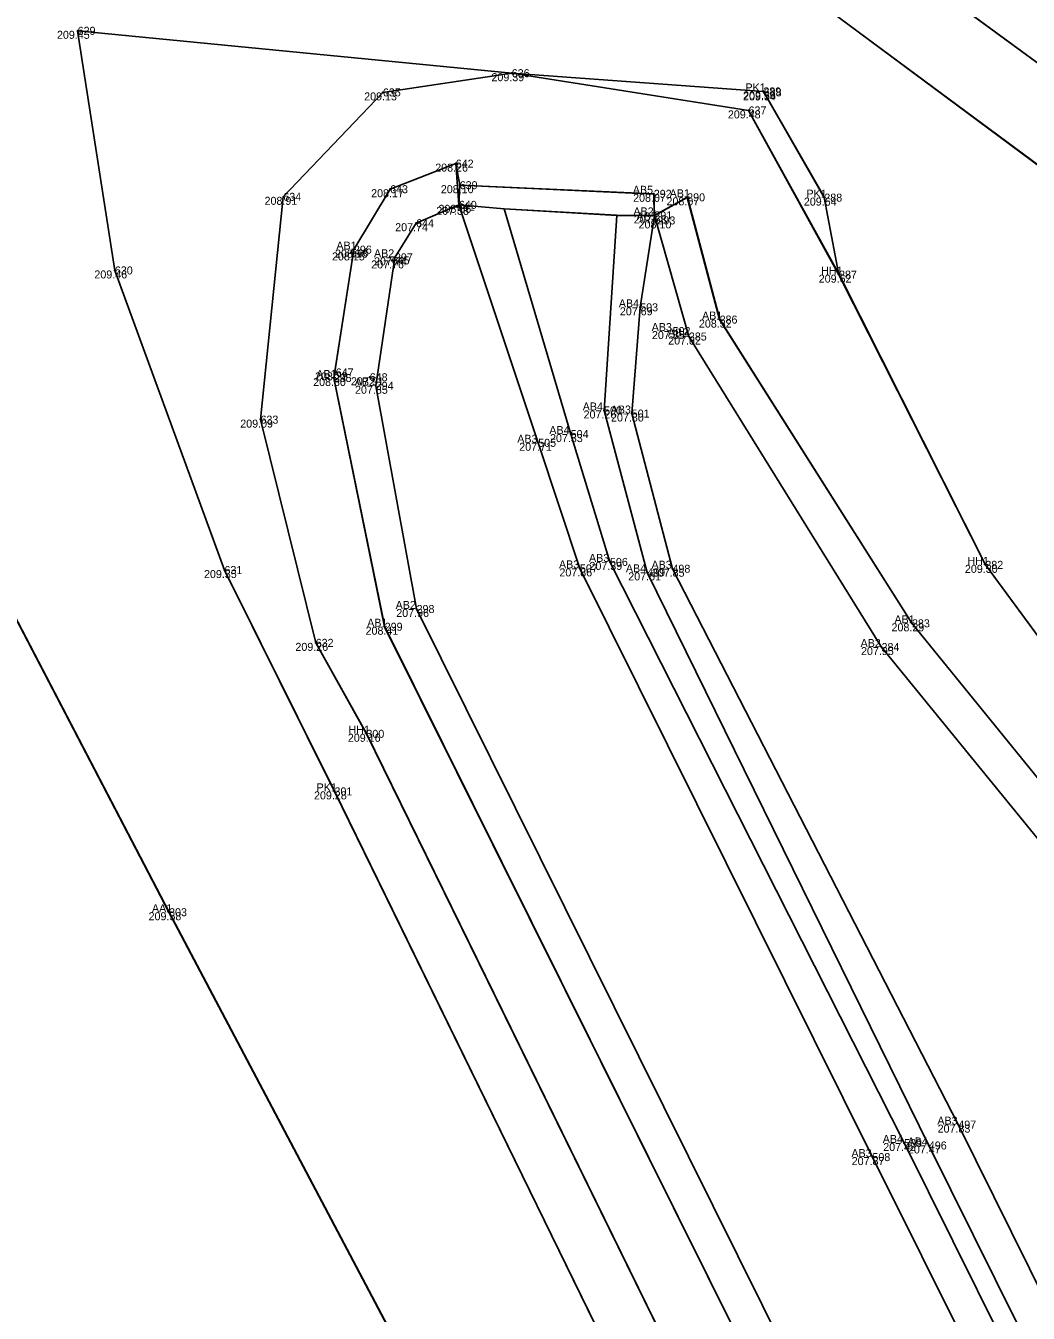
# Model space of a CAD drawing. Extents: x -263091 to -262565, y -1238731 to -1237092.
# Drawn here: x -262955.92 to -262930.86, y -1238442.76 to -1238410.57 of the extents above; entities that cross this region are included whole.
import ezdxf

# ---------------------------------------------------------------- set-up
doc = ezdxf.new("R2010")
doc.units = 0
for name, color, linetype in [('01_Hrana_betónu', 7, 'Continuous'), ('02_Oplotenie', 7, 'Continuous'), ('03_Asfalt', 7, 'Continuous'), ('05_Hrana_terénu', 7, 'Continuous'), ('07_Iné', 7, 'Continuous'), ('10', 7, 'Continuous'), ('Groma (21)', 7, 'Continuous'), ('Groma (22)', 7, 'Continuous'), ('Groma (23)', 7, 'Continuous'), ('Groma (24)', 7, 'Continuous'), ('U001_Betónové_panely_oblast', 7, 'Continuous'), ('U001_Betóny_prídavné', 7, 'Continuous'), ('U001_Zeleň_mimo', 7, 'Continuous'), ('U001_Zeleň_vnútro', 7, 'Continuous'), ('U001_Zeleň_zatrávňovač', 7, 'Continuous'), ('U002_Asfalt', 7, 'Continuous'), ('U002_Zeleň_mimo', 7, 'Continuous')]:
    doc.layers.add(name, color=color, linetype=linetype)

msp = doc.modelspace()

# ---------------------------------------------------------------- linework, layer by layer
at = {"layer": '01_Hrana_betónu'}
for points in [[(-262945.17, -1238414.02), (-262946.81, -1238414.66), (-262947.715, -1238416.17), (-262948.218, -1238419.379), (-262946.945, -1238425.597), (-262935.208, -1238449.194), (-262927.854, -1238464.094), (-262916.808, -1238486.576), (-262907.486, -1238505.358), (-262899.299, -1238522.3), (-262896.198, -1238529.903), (-262891.697, -1238541.993), (-262882.447, -1238561.681), (-262873.377, -1238580.679), (-262868.934, -1238589.993), (-262864.101, -1238600.869)], [(-262863.262, -1238600.529), (-262868.088, -1238589.608), (-262872.609, -1238580.269), (-262881.626, -1238561.239), (-262890.834, -1238541.618), (-262895.354, -1238529.529), (-262898.372, -1238521.954), (-262906.659, -1238504.862), (-262915.915, -1238486.239), (-262927.038, -1238463.656), (-262934.41, -1238448.791), (-262946.148, -1238425.153), (-262947.17, -1238419.573), (-262946.689, -1238416.363), (-262946.16, -1238415.51), (-262945.09, -1238415.05), (-262945.17, -1238414.02)], [(-262945.09, -1238415.05), (-262943.108, -1238420.999), (-262942.065, -1238424.139), (-262934.754, -1238438.855), (-262923.683, -1238461.06), (-262913.753, -1238481.232), (-262903.896, -1238501.06), (-262894.759, -1238519.856), (-262890.317, -1238530.551), (-262883.158, -1238545.169), (-262873.572, -1238564.111), (-262869.728, -1238571.951), (-262860.562, -1238590.864), (-262854.835, -1238604.812), (-262840.38, -1238642.586), (-262833.174, -1238661.935), (-262826.575, -1238681.018), (-262825.738, -1238690.053), (-262824.527, -1238692.082)], [(-262919.416, -1238445.121), (-262926.823, -1238435.554), (-262934.526, -1238426.105), (-262939.342, -1238418.342), (-262940.205, -1238415.315), (-262939.384, -1238414.863)], [(-262939.384, -1238414.863), (-262938.574, -1238417.919), (-262933.765, -1238425.512), (-262926.119, -1238434.921), (-262918.733, -1238444.559)], [(-262821.464, -1238691.979), (-262823.978, -1238691.385), (-262824.893, -1238689.953), (-262825.729, -1238680.825), (-262832.468, -1238661.625), (-262839.672, -1238642.452), (-262854.271, -1238604.655), (-262859.863, -1238590.55), (-262868.949, -1238571.69), (-262872.864, -1238563.867), (-262882.403, -1238544.934), (-262889.591, -1238530.296), (-262894.035, -1238519.557), (-262903.102, -1238500.748), (-262912.912, -1238480.97), (-262922.987, -1238460.594), (-262933.962, -1238438.502), (-262941.314, -1238423.977), (-262942.296, -1238420.781), (-262943.962, -1238415.15)], [(-262941.142, -1238415.313), (-262941.461, -1238420.191), (-262940.383, -1238424.238), (-262933.343, -1238438.564), (-262922.27, -1238460.876), (-262912.449, -1238480.877), (-262902.557, -1238500.683), (-262893.416, -1238519.552), (-262889.058, -1238529.686), (-262881.962, -1238544.577), (-262872.106, -1238564.019), (-262868.478, -1238571.232), (-262859.211, -1238590.61), (-262852.998, -1238605.343), (-262846.933, -1238621.173), (-262838.559, -1238643.348), (-262831.894, -1238661.158), (-262825.164, -1238680.62), (-262824.312, -1238689.696), (-262823.847, -1238690.483), (-262822.763, -1238690.91), (-262821.486, -1238690.803)], [(-262821.555, -1238690.42), (-262822.731, -1238690.203), (-262823.426, -1238689.509), (-262824.318, -1238680.43), (-262831.163, -1238660.976), (-262837.946, -1238643.111), (-262846.365, -1238620.94), (-262852.333, -1238605.156), (-262858.618, -1238590.245), (-262867.784, -1238570.905), (-262871.416, -1238563.68), (-262881.223, -1238544.283), (-262888.392, -1238529.442), (-262892.626, -1238519.239), (-262901.725, -1238500.385), (-262911.6, -1238480.51), (-262921.479, -1238460.51), (-262932.607, -1238438.043), (-262939.752, -1238424.147), (-262940.771, -1238420.267), (-262940.559, -1238417.612), (-262940.205, -1238415.315)]]:
    msp.add_lwpolyline(points, dxfattribs=at)
at = {"layer": '02_Oplotenie'}
msp.add_lwpolyline([(-262935.956, -1238414.87), (-262937.48, -1238412.215), (-262943.77, -1238411.76), (-262954.62, -1238410.7), (-262953.69, -1238416.69), (-262950.95, -1238424.18), (-262948.2, -1238429.713), (-262938.076, -1238450.416), (-262931.824, -1238462.793)], dxfattribs=at)
at = {"layer": '03_Asfalt'}
for points in [[(-262913.444, -1238391.676), (-262911.985, -1238397.337), (-262910.006, -1238403.107), (-262907.769, -1238409.039), (-262901.709, -1238424.56), (-262896.942, -1238436.871), (-262897.547, -1238437.016), (-262898.706, -1238436.381), (-262904.848, -1238431.522), (-262916.36, -1238422.355), (-262927.608, -1238413.712), (-262940.472, -1238404.296), (-262944.235, -1238401.54), (-262944.94, -1238400.579), (-262945.063, -1238399.495), (-262942.635, -1238399.58), (-262939.962, -1238399.183), (-262936.84, -1238398.276), (-262934.121, -1238396.673), (-262931.78, -1238394.73), (-262927.567, -1238384.599)], [(-262974.83, -1238389.493), (-262966.434, -1238405.689), (-262952.335, -1238432.734), (-262942.188, -1238451.946), (-262934.983, -1238466.187), (-262921.957, -1238491.107), (-262911.861, -1238511.116), (-262905.822, -1238523.977), (-262900.647, -1238535.669), (-262888.764, -1238565.07), (-262881.2, -1238585.494), (-262874.644, -1238603.324)], [(-262804.465, -1238690.033), (-262818.631, -1238655.736), (-262826.695, -1238636.389), (-262836.855, -1238611.872), (-262842.406, -1238598.306), (-262850.452, -1238578.707), (-262858.82, -1238561.234), (-262870.509, -1238539), (-262873.344, -1238533.53), (-262876.375, -1238529.239), (-262880.031, -1238521.826), (-262869.115, -1238517.45), (-262870.175, -1238508.052), (-262871.319, -1238501.744), (-262886.895, -1238462.375), (-262895.067, -1238441.663), (-262905.824, -1238433.621), (-262917.716, -1238423.993), (-262928.896, -1238415.327), (-262941.774, -1238405.784), (-262954.673, -1238396.412), (-262962.054, -1238391.026)]]:
    msp.add_lwpolyline(points, dxfattribs=at)
at = {"layer": '05_Hrana_terénu'}
msp.add_lwpolyline([(-262927.783, -1238467.254), (-262930.465, -1238462.525), (-262936.779, -1238449.928), (-262947.402, -1238428.273), (-262948.67, -1238426), (-262950.05, -1238420.42), (-262949.48, -1238414.85), (-262946.99, -1238412.24), (-262943.77, -1238411.76), (-262937.85, -1238412.69), (-262935.589, -1238416.796), (-262931.931, -1238424.05), (-262925.295, -1238433.06), (-262918.113, -1238442.283), (-262917.125, -1238443.234)], dxfattribs=at)
at = {"layer": '07_Iné'}
msp.add_lwpolyline([(-262945.07, -1238414.56), (-262945.09, -1238415.05), (-262945.09, -1238415.05), (-262943.962, -1238415.15), (-262941.142, -1238415.313), (-262940.205, -1238415.315), (-262940.205, -1238415.315), (-262940.219, -1238414.775)], close=True, dxfattribs=at)
at = {"layer": '10'}
msp.add_lwpolyline([(-262982.434, -1238375.977), (-262968.907, -1238386.238), (-262962.054, -1238391.026), (-262954.673, -1238396.412), (-262941.774, -1238405.784), (-262928.896, -1238415.327), (-262917.716, -1238423.993), (-262905.824, -1238433.621), (-262895.067, -1238441.663), (-262870.407, -1238460.6)], dxfattribs=at)
at = {"layer": 'Groma (21)'}
for centre in [(-262954.62, -1238410.7), (-262943.77, -1238411.76), (-262937.48, -1238412.215), (-262946.99, -1238412.24), (-262937.47, -1238412.24), (-262937.85, -1238412.69), (-262945.17, -1238414.02), (-262946.81, -1238414.66), (-262945.07, -1238414.56), (-262940.219, -1238414.775), (-262949.48, -1238414.85), (-262945.14, -1238415.1), (-262945.09, -1238415.05), (-262939.384, -1238414.863), (-262935.956, -1238414.87), (-262940.205, -1238415.315), (-262946.16, -1238415.51), (-262940.127, -1238415.44), (-262947.79, -1238416.24), (-262947.715, -1238416.17), (-262946.689, -1238416.363), (-262953.69, -1238416.69), (-262946.77, -1238416.44), (-262935.589, -1238416.796), (-262940.559, -1238417.612), (-262938.574, -1238417.919), (-262939.748, -1238418.206), (-262939.342, -1238418.342), (-262948.17, -1238419.24), (-262948.218, -1238419.379), (-262947.32, -1238419.36), (-262947.17, -1238419.573), (-262941.461, -1238420.191), (-262940.771, -1238420.267), (-262950.05, -1238420.42), (-262942.296, -1238420.781), (-262943.108, -1238420.999), (-262941.314, -1238423.977), (-262931.931, -1238424.05), (-262950.95, -1238424.18), (-262942.065, -1238424.139), (-262940.383, -1238424.238), (-262939.752, -1238424.147), (-262946.148, -1238425.153), (-262946.945, -1238425.597), (-262933.765, -1238425.512), (-262948.67, -1238426), (-262934.526, -1238426.105), (-262947.402, -1238428.273), (-262948.2, -1238429.713), (-262952.335, -1238432.734), (-262932.607, -1238438.043), (-262933.962, -1238438.502), (-262933.343, -1238438.564), (-262934.754, -1238438.855)]:
    msp.add_circle(centre, 0.01, dxfattribs=at)
at = {"layer": 'U001_Betónové_panely_oblast'}
msp.add_lwpolyline([(-262907.49, -1238505.36), (-262916.81, -1238486.58), (-262927.85, -1238464.09), (-262935.21, -1238449.19), (-262946.95, -1238425.6), (-262948.22, -1238419.38), (-262947.72, -1238416.17), (-262946.81, -1238414.66), (-262945.17, -1238414.02), (-262945.09, -1238415.05), (-262943.96, -1238415.15), (-262941.14, -1238415.31), (-262940.21, -1238415.32), (-262939.38, -1238414.86), (-262938.57, -1238417.92), (-262933.77, -1238425.51), (-262926.12, -1238434.92), (-262918.73, -1238444.56), (-262919.42, -1238445.12), (-262914.36, -1238451.38), (-262913.6, -1238450.89), (-262908.88, -1238459.13), (-262904.31, -1238470.05)], dxfattribs=at)
msp.add_lwpolyline([(-262907.49, -1238505.36), (-262916.81, -1238486.58), (-262927.85, -1238464.09), (-262935.21, -1238449.19), (-262946.95, -1238425.6), (-262948.22, -1238419.38), (-262947.72, -1238416.17), (-262946.81, -1238414.66), (-262945.17, -1238414.02), (-262945.09, -1238415.05), (-262943.96, -1238415.15), (-262941.14, -1238415.31), (-262940.21, -1238415.32), (-262939.38, -1238414.86), (-262938.57, -1238417.92), (-262933.77, -1238425.51), (-262926.12, -1238434.92), (-262918.73, -1238444.56), (-262919.42, -1238445.12), (-262914.36, -1238451.38), (-262913.6, -1238450.89), (-262908.88, -1238459.13), (-262904.31, -1238470.05)], dxfattribs=at)
at = {"layer": 'U001_Betóny_prídavné'}
msp.add_lwpolyline([(-262943.96, -1238415.15), (-262945.09, -1238415.05), (-262945.07, -1238414.56), (-262940.22, -1238414.78), (-262940.21, -1238415.32), (-262941.14, -1238415.31)], close=True, dxfattribs=at)
msp.add_lwpolyline([(-262940.21, -1238415.32), (-262941.14, -1238415.31), (-262943.96, -1238415.15), (-262945.09, -1238415.05), (-262945.07, -1238414.56), (-262940.22, -1238414.78), (-262940.21, -1238415.32)], dxfattribs=at)
at = {"layer": 'U001_Zeleň_mimo'}
for points in [[(-262874.64, -1238603.32), (-262881.2, -1238585.49), (-262888.76, -1238565.07), (-262900.65, -1238535.67), (-262905.82, -1238523.98), (-262911.86, -1238511.12), (-262921.96, -1238491.11), (-262934.98, -1238466.19), (-262942.19, -1238451.95), (-262952.34, -1238432.73), (-262966.43, -1238405.69), (-262974.83, -1238389.49)], [(-262962.05, -1238391.03), (-262954.67, -1238396.41), (-262941.77, -1238405.78), (-262928.9, -1238415.33), (-262917.72, -1238423.99), (-262905.82, -1238433.62), (-262895.07, -1238441.66), (-262886.9, -1238462.38), (-262871.32, -1238501.74), (-262870.18, -1238508.05), (-262869.12, -1238517.45), (-262880.03, -1238521.83), (-262876.38, -1238529.24), (-262873.34, -1238533.53), (-262870.51, -1238539), (-262858.82, -1238561.23), (-262850.45, -1238578.71), (-262842.41, -1238598.31), (-262836.86, -1238611.87), (-262826.7, -1238636.39), (-262818.63, -1238655.74), (-262804.47, -1238690.03)], [(-262902.96, -1238468.81), (-262907.91, -1238457.21), (-262911.31, -1238451.07), (-262911.84, -1238449.79), (-262917.13, -1238443.23), (-262918.11, -1238442.28), (-262925.3, -1238433.06), (-262931.93, -1238424.05), (-262935.59, -1238416.8), (-262935.96, -1238414.87), (-262937.48, -1238412.22), (-262943.77, -1238411.76), (-262954.62, -1238410.7), (-262953.69, -1238416.69), (-262950.95, -1238424.18), (-262948.2, -1238429.71), (-262938.08, -1238450.42), (-262931.82, -1238462.79), (-262930.86, -1238463.25), (-262933.04, -1238464.36), (-262929.78, -1238468.68), (-262929.26, -1238468.08), (-262919.31, -1238488.27), (-262908.34, -1238509.94)]]:
    msp.add_lwpolyline(points, dxfattribs=at)
at = {"layer": 'U001_Zeleň_vnútro'}
for points in [[(-262908.34, -1238509.94), (-262919.31, -1238488.27), (-262929.26, -1238468.08), (-262927.92, -1238467.26), (-262930.86, -1238463.25), (-262931.82, -1238462.79), (-262938.08, -1238450.42), (-262948.2, -1238429.71), (-262950.95, -1238424.18), (-262953.69, -1238416.69), (-262954.62, -1238410.7), (-262943.77, -1238411.76), (-262946.99, -1238412.24), (-262949.48, -1238414.85), (-262950.05, -1238420.42), (-262948.67, -1238426), (-262947.4, -1238428.27), (-262936.78, -1238449.93), (-262930.47, -1238462.53), (-262927.78, -1238467.25), (-262927.47, -1238468.81), (-262918.2, -1238487.16), (-262908.25, -1238507.59)], [(-262908.34, -1238509.94), (-262919.31, -1238488.27), (-262929.26, -1238468.08), (-262927.92, -1238467.26), (-262930.86, -1238463.25), (-262931.82, -1238462.79), (-262938.08, -1238450.42), (-262948.2, -1238429.71), (-262950.95, -1238424.18), (-262953.69, -1238416.69), (-262954.62, -1238410.7), (-262943.77, -1238411.76), (-262946.99, -1238412.24), (-262949.48, -1238414.85), (-262950.05, -1238420.42), (-262948.67, -1238426), (-262947.4, -1238428.27), (-262936.78, -1238449.93), (-262930.47, -1238462.53), (-262927.78, -1238467.25), (-262927.47, -1238468.81), (-262918.2, -1238487.16), (-262908.25, -1238507.59)], [(-262935.96, -1238414.87), (-262935.59, -1238416.8), (-262937.85, -1238412.69), (-262943.77, -1238411.76), (-262937.48, -1238412.22), (-262935.96, -1238414.87)]]:
    msp.add_lwpolyline(points, dxfattribs=at)
msp.add_lwpolyline([(-262935.59, -1238416.8), (-262937.85, -1238412.69), (-262943.77, -1238411.76), (-262937.48, -1238412.22), (-262935.96, -1238414.87)], close=True, dxfattribs=at)
at = {"layer": 'U001_Zeleň_zatrávňovač'}
for points in [[(-262936.78, -1238449.93), (-262947.4, -1238428.27), (-262948.67, -1238426), (-262950.05, -1238420.42), (-262949.48, -1238414.85), (-262946.99, -1238412.24), (-262943.77, -1238411.76), (-262937.85, -1238412.69), (-262935.59, -1238416.8), (-262931.93, -1238424.05), (-262925.3, -1238433.06), (-262918.11, -1238442.28), (-262917.13, -1238443.23)], [(-262936.78, -1238449.93), (-262947.4, -1238428.27), (-262948.67, -1238426), (-262950.05, -1238420.42), (-262949.48, -1238414.85), (-262946.99, -1238412.24), (-262943.77, -1238411.76), (-262937.85, -1238412.69), (-262935.59, -1238416.8), (-262931.93, -1238424.05), (-262925.3, -1238433.06), (-262918.11, -1238442.28), (-262917.13, -1238443.23)], [(-262918.73, -1238444.56), (-262926.12, -1238434.92), (-262933.77, -1238425.51), (-262938.57, -1238417.92), (-262939.38, -1238414.86), (-262940.21, -1238415.32), (-262940.22, -1238414.78), (-262945.07, -1238414.56), (-262945.17, -1238414.02), (-262946.81, -1238414.66), (-262947.72, -1238416.17), (-262948.22, -1238419.38), (-262946.95, -1238425.6), (-262935.21, -1238449.19)], [(-262918.73, -1238444.56), (-262926.12, -1238434.92), (-262933.77, -1238425.51), (-262938.57, -1238417.92), (-262939.38, -1238414.86), (-262940.21, -1238415.32), (-262940.22, -1238414.78), (-262945.07, -1238414.56), (-262945.17, -1238414.02), (-262946.81, -1238414.66), (-262947.72, -1238416.17), (-262948.22, -1238419.38), (-262946.95, -1238425.6), (-262935.21, -1238449.19)]]:
    msp.add_lwpolyline(points, dxfattribs=at)
at = {"layer": 'U002_Asfalt'}
for points in [[(-262927.57, -1238384.6), (-262931.78, -1238394.73), (-262934.12, -1238396.67), (-262936.84, -1238398.28), (-262939.96, -1238399.18), (-262942.64, -1238399.58), (-262945.06, -1238399.5), (-262944.94, -1238400.58), (-262944.24, -1238401.54), (-262940.47, -1238404.3), (-262927.61, -1238413.71), (-262916.36, -1238422.36), (-262904.85, -1238431.52), (-262898.71, -1238436.38), (-262897.55, -1238437.02), (-262896.94, -1238436.87), (-262895.07, -1238441.66), (-262905.82, -1238433.62), (-262917.72, -1238423.99), (-262928.9, -1238415.33), (-262941.77, -1238405.78), (-262954.67, -1238396.41), (-262962.05, -1238391.03)], [(-262927.57, -1238384.6), (-262931.78, -1238394.73), (-262934.12, -1238396.67), (-262936.84, -1238398.28), (-262939.96, -1238399.18), (-262942.64, -1238399.58), (-262945.06, -1238399.5), (-262944.94, -1238400.58), (-262944.24, -1238401.54), (-262940.47, -1238404.3), (-262927.61, -1238413.71), (-262916.36, -1238422.36), (-262904.85, -1238431.52), (-262898.71, -1238436.38), (-262897.55, -1238437.02), (-262896.94, -1238436.87), (-262895.07, -1238441.66)], [(-262895.07, -1238441.66), (-262905.82, -1238433.62), (-262917.72, -1238423.99), (-262928.9, -1238415.33), (-262941.77, -1238405.78), (-262954.67, -1238396.41), (-262962.05, -1238391.03)]]:
    msp.add_lwpolyline(points, dxfattribs=at)
at = {"layer": 'U002_Zeleň_mimo'}
msp.add_lwpolyline([(-262913.44, -1238391.68), (-262911.99, -1238397.34), (-262910.01, -1238403.11), (-262907.77, -1238409.04), (-262901.71, -1238424.56), (-262896.94, -1238436.87), (-262897.55, -1238437.02), (-262898.71, -1238436.38), (-262904.85, -1238431.52), (-262916.36, -1238422.36), (-262927.61, -1238413.71), (-262940.47, -1238404.3), (-262944.24, -1238401.54), (-262944.94, -1238400.58), (-262945.06, -1238399.5), (-262942.64, -1238399.58), (-262939.96, -1238399.18), (-262936.84, -1238398.28), (-262934.12, -1238396.67), (-262931.78, -1238394.73), (-262927.57, -1238384.6)], dxfattribs=at)

# ---------------------------------------------------------------- texts
at = {"layer": 'Groma (22)'}
for s, p in [('629', (-262954.62, -1238410.8)), ('636', (-262943.77, -1238411.86)), ('635', (-262946.99, -1238412.34)), ('289', (-262937.48, -1238412.315)), ('638', (-262937.47, -1238412.34)), ('637', (-262937.85, -1238412.79)), ('642', (-262945.17, -1238414.12)), ('639', (-262945.07, -1238414.66)), ('634', (-262949.48, -1238414.95)), ('643', (-262946.81, -1238414.76)), ('292', (-262940.219, -1238414.875)), ('290', (-262939.384, -1238414.963)), ('288', (-262935.956, -1238414.97)), ('641', (-262945.14, -1238415.2)), ('640', (-262945.09, -1238415.15)), ('644', (-262946.16, -1238415.61)), ('291', (-262940.205, -1238415.415)), ('293', (-262940.127, -1238415.54)), ('296', (-262947.715, -1238416.27)), ('646', (-262947.79, -1238416.34)), ('645', (-262946.77, -1238416.54)), ('297', (-262946.689, -1238416.463)), ('630', (-262953.69, -1238416.79)), ('287', (-262935.589, -1238416.896)), ('503', (-262940.559, -1238417.712)), ('286', (-262938.574, -1238418.019)), ('502', (-262939.748, -1238418.306)), ('285', (-262939.342, -1238418.442)), ('295', (-262948.218, -1238419.479)), ('647', (-262948.17, -1238419.34)), ('648', (-262947.32, -1238419.46)), ('294', (-262947.17, -1238419.673)), ('500', (-262941.461, -1238420.291)), ('501', (-262940.771, -1238420.367)), ('633', (-262950.05, -1238420.52)), ('505', (-262943.108, -1238421.099)), ('504', (-262942.296, -1238420.881)), ('631', (-262950.95, -1238424.28)), ('507', (-262942.065, -1238424.239)), ('506', (-262941.314, -1238424.077)), ('498', (-262939.752, -1238424.247)), ('282', (-262931.931, -1238424.15)), ('499', (-262940.383, -1238424.338)), ('298', (-262946.148, -1238425.253)), ('299', (-262946.945, -1238425.697)), ('283', (-262933.765, -1238425.612)), ('632', (-262948.67, -1238426.1)), ('284', (-262934.526, -1238426.205)), ('300', (-262947.402, -1238428.373)), ('301', (-262948.2, -1238429.813)), ('303', (-262952.335, -1238432.834)), ('497', (-262932.607, -1238438.143)), ('509', (-262933.962, -1238438.602)), ('496', (-262933.343, -1238438.664)), ('508', (-262934.754, -1238438.955))]:
    msp.add_text(s, height=0.2, dxfattribs=at).set_placement(p)
at = {"layer": 'Groma (23)'}
for s, p in [('209.45', (-262955.137, -1238410.9)), ('209.39', (-262944.277, -1238411.96)), ('209.13', (-262947.458, -1238412.44)), ('209.56', (-262937.987, -1238412.415)), ('209.54', (-262937.987, -1238412.44)), ('209.48', (-262938.367, -1238412.89)), ('208.26', (-262945.682, -1238414.22)), ('208.17', (-262947.284, -1238414.86)), ('208.10', (-262945.542, -1238414.76)), ('208.07', (-262940.736, -1238414.975)), ('208.91', (-262949.948, -1238415.05)), ('207.58', (-262945.657, -1238415.3)), ('208.06', (-262945.601, -1238415.25)), ('208.07', (-262939.901, -1238415.063)), ('209.64', (-262936.468, -1238415.07)), ('207.63', (-262940.718, -1238415.515)), ('207.74', (-262946.683, -1238415.71)), ('208.10', (-262940.599, -1238415.64)), ('208.15', (-262948.263, -1238416.44)), ('208.18', (-262948.188, -1238416.37)), ('207.74', (-262947.212, -1238416.563)), ('209.46', (-262954.202, -1238416.89)), ('207.76', (-262947.283, -1238416.64)), ('209.62', (-262936.096, -1238416.996)), ('207.69', (-262941.067, -1238417.812)), ('208.32', (-262939.091, -1238418.119)), ('207.85', (-262940.265, -1238418.406)), ('207.82', (-262939.859, -1238418.542)), ('208.28', (-262948.687, -1238419.44)), ('208.30', (-262948.734, -1238419.579)), ('207.91', (-262947.789, -1238419.56)), ('207.85', (-262947.687, -1238419.773)), ('207.26', (-262941.974, -1238420.391)), ('209.09', (-262950.556, -1238420.62)), ('207.80', (-262941.288, -1238420.467)), ('207.33', (-262942.813, -1238420.981)), ('207.71', (-262943.583, -1238421.199)), ('207.39', (-262941.827, -1238424.177)), ('209.30', (-262932.442, -1238424.25)), ('209.35', (-262951.462, -1238424.38)), ('207.86', (-262942.578, -1238424.339)), ('207.51', (-262940.857, -1238424.438)), ('207.85', (-262940.269, -1238424.347)), ('207.96', (-262946.656, -1238425.353)), ('208.41', (-262947.423, -1238425.797)), ('208.29', (-262934.277, -1238425.712)), ('209.26', (-262949.177, -1238426.2)), ('207.95', (-262935.039, -1238426.305)), ('209.16', (-262947.866, -1238428.473)), ('209.28', (-262948.712, -1238429.913)), ('209.58', (-262952.847, -1238432.934)), ('207.83', (-262933.124, -1238438.243)), ('207.48', (-262934.484, -1238438.702)), ('207.47', (-262933.866, -1238438.764)), ('207.87', (-262935.272, -1238439.055))]:
    msp.add_text(s, height=0.2, dxfattribs=at).set_placement(p)
at = {"layer": 'Groma (24)'}
for s, p in [('PK1', (-262937.927, -1238412.215)), ('AB5', (-262940.743, -1238414.775)), ('AB1', (-262939.822, -1238414.863)), ('PK1', (-262936.403, -1238414.87)), ('AB2', (-262940.729, -1238415.315)), ('AB5', (-262940.651, -1238415.44)), ('AB1', (-262948.153, -1238416.17)), ('AB2', (-262947.213, -1238416.363)), ('HH1', (-262936.036, -1238416.796)), ('AB4', (-262941.093, -1238417.612)), ('AB3', (-262940.272, -1238418.206)), ('AB1', (-262939.012, -1238417.919)), ('AB2', (-262939.866, -1238418.342)), ('AB1', (-262948.656, -1238419.379)), ('AB2', (-262947.694, -1238419.573)), ('AB4', (-262941.995, -1238420.191)), ('AB3', (-262941.295, -1238420.267)), ('AB3', (-262943.632, -1238420.999)), ('AB4', (-262942.83, -1238420.781)), ('AB3', (-262941.838, -1238423.977)), ('AB3', (-262942.589, -1238424.139)), ('AB4', (-262940.917, -1238424.238)), ('AB3', (-262940.276, -1238424.147)), ('HH1', (-262932.378, -1238424.05)), ('AB2', (-262946.672, -1238425.153)), ('AB1', (-262947.383, -1238425.597)), ('AB1', (-262934.203, -1238425.512)), ('AB2', (-262935.05, -1238426.105)), ('HH1', (-262947.849, -1238428.273)), ('PK1', (-262948.647, -1238429.713)), ('AA1', (-262952.763, -1238432.734)), ('AB3', (-262933.131, -1238438.043)), ('AB4', (-262934.496, -1238438.502)), ('AB4', (-262933.877, -1238438.564)), ('AB3', (-262935.278, -1238438.855))]:
    msp.add_text(s, height=0.2, dxfattribs=at).set_placement(p)

doc.saveas('drawing.dxf')
